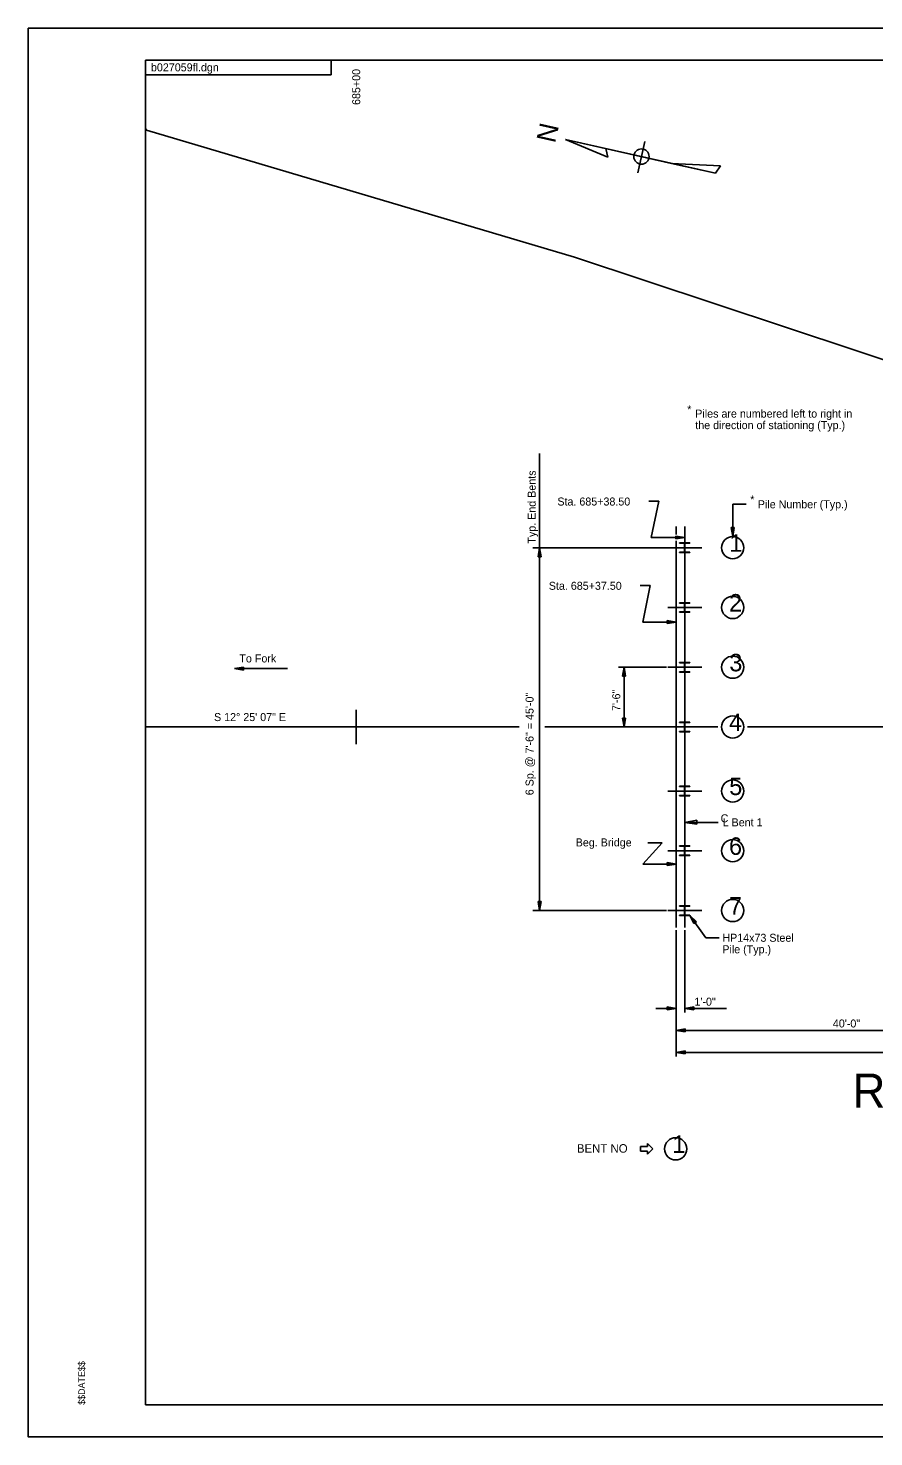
# Model space of a CAD drawing. Extents: x -463 to -191, y 251 to 416.
# Drawn here: x -462.9 to -363.8, y 251.4 to 416.4 of the extents above; entities that cross this region are included whole.
import ezdxf

# ---------------------------------------------------------------- set-up
doc = ezdxf.new("R2010")
doc.units = 0
for name, color, linetype in [('BR_AUTO DIMENSION', 7, 'Continuous'), ('BR_BORDER LINES', 7, 'Continuous'), ('BR_STRUCTURAL STEEL', 7, 'Continuous'), ('BR_TEXT', 7, 'Continuous'), ('Default', 7, 'Continuous'), ('RD_SHT_IplotShp', 7, 'Continuous')]:
    doc.layers.add(name, color=color, linetype=linetype)

# ---------------------------------------------------------------- blocks, each defined once
blk = doc.blocks.new('ARROW1')
at = {"layer": 'Default'}
for p, q in [((0.0001, 33.5999), (-14.3999, 19.1999)), ((-14.3999, 19.1999), (-6.3999, 19.1999)), ((-6.3999, 19.1999), (-6.3999, -0.0001)), ((14.4001, 19.1999), (0.0001, 33.5999)), ((6.4001, -0.0001), (6.4001, 19.1999)), ((6.4001, 19.1999), (14.4001, 19.1999)), ((-6.3999, -0.0001), (6.4001, -0.0001))]:
    blk.add_line(p, q, dxfattribs=at)

msp = doc.modelspace()

# ---------------------------------------------------------------- linework, layer by layer
at = {"layer": 'BR_AUTO DIMENSION'}
for p, q in [((-382.36, 399.46), (-399.92, 403.41)), ((-399.92, 403.41), (-394.95, 401.34)), ((-382.36, 399.46), (-399.92, 403.41)), ((-399.92, 403.41), (-387.5, 400.61)), ((-399.92, 403.41), (-394.95, 401.34)), ((-399.92, 403.41), (-382.36, 399.46)), ((-382.36, 399.46), (-399.92, 403.41)), ((-390.62, 403.18), (-391.45, 399.5)), ((-394.95, 401.34), (-395.18, 402.34)), ((-394.95, 401.34), (-395.18, 402.34)), ((-381.76, 400.32), (-387.5, 400.61)), ((-382.36, 399.46), (-387.5, 400.61)), ((-387.5, 400.61), (-381.76, 400.32)), ((-387.5, 400.61), (-381.76, 400.32)), ((-382.36, 399.46), (-381.76, 400.32)), ((-381.76, 400.32), (-382.36, 399.46)), ((-381.76, 400.32), (-382.36, 399.46)), ((-402.95, 313.09), (-402.95, 366.63)), ((-390.17, 361.05), (-388.98, 361.05)), ((-388.98, 361.05), (-389.86, 356.78)), ((-380.32, 360.69), (-378.76, 360.69)), ((-380.32, 360.69), (-380.32, 356.89)), ((-385.94, 356.78), (-389.86, 356.78)), ((-385.94, 356.78), (-387, 356.96)), ((-387, 356.96), (-387, 356.61)), ((-387, 356.61), (-385.94, 356.78)), ((-380.32, 356.89), (-380.5, 357.94)), ((-380.5, 357.94), (-380.15, 357.94)), ((-380.15, 357.94), (-380.32, 356.89)), ((-403.76, 355.59), (-388.09, 355.59)), ((-402.95, 355.59), (-403.12, 354.53)), ((-402.77, 354.53), (-402.95, 355.59)), ((-388.09, 355.59), (-387.94, 355.59)), ((-403.12, 354.53), (-402.77, 354.53)), ((-391.17, 351.17), (-389.98, 351.17)), ((-389.98, 351.17), (-390.86, 346.88)), ((-386.95, 346.88), (-390.86, 346.88)), ((-386.95, 346.88), (-388, 347.06)), ((-388, 347.06), (-388, 346.7)), ((-388, 346.7), (-386.95, 346.88)), ((-438.71, 341.43), (-437.65, 341.61)), ((-437.65, 341.61), (-437.65, 341.26)), ((-393.71, 341.59), (-388.09, 341.59)), ((-393.22, 340.53), (-393.04, 341.59)), ((-393.04, 334.59), (-393.04, 341.59)), ((-393.04, 341.59), (-392.87, 340.53)), ((-437.65, 341.26), (-438.71, 341.43)), ((-438.71, 341.43), (-432.51, 341.43)), ((-392.87, 340.53), (-393.22, 340.53)), ((-392.87, 335.64), (-393.22, 335.64)), ((-393.22, 335.64), (-393.04, 334.59)), ((-393.04, 334.59), (-392.87, 335.64)), ((-385.94, 323.42), (-384.54, 323.66)), ((-382.03, 323.42), (-385.94, 323.42)), ((-384.54, 323.19), (-385.94, 323.42)), ((-384.54, 323.66), (-384.54, 323.19)), ((-388.61, 321.02), (-390.85, 318.53)), ((-390.28, 321.02), (-388.61, 321.02)), ((-386.93, 318.53), (-390.85, 318.53)), ((-386.93, 318.53), (-387.99, 318.71)), ((-387.99, 318.71), (-387.99, 318.36)), ((-387.99, 318.36), (-386.93, 318.53)), ((-402.95, 313.09), (-403.12, 314.14)), ((-403.12, 314.14), (-402.77, 314.14)), ((-402.77, 314.14), (-402.95, 313.09)), ((-403.76, 313.09), (-388.09, 313.09)), ((-383.47, 309.88), (-385.33, 312.52)), ((-385.33, 312.52), (-384.87, 311.56)), ((-384.58, 311.76), (-385.33, 312.52)), ((-386.94, 310.78), (-386.94, 295.98)), ((-385.94, 310.78), (-385.94, 301.13)), ((-384.87, 311.56), (-384.58, 311.76)), ((-383.47, 309.88), (-381.91, 309.88)), ((-389.33, 301.63), (-386.94, 301.63)), ((-388, 301.45), (-388, 301.8)), ((-388, 301.8), (-386.94, 301.63)), ((-386.94, 301.63), (-388, 301.45)), ((-384.89, 301.8), (-385.94, 301.63)), ((-385.94, 301.63), (-381.05, 301.63)), ((-385.94, 301.63), (-384.89, 301.45)), ((-384.89, 301.45), (-384.89, 301.8)), ((-386.94, 299.05), (-385.89, 299.22)), ((-386.94, 299.05), (-256.94, 299.05)), ((-385.89, 298.87), (-386.94, 299.05)), ((-385.89, 299.22), (-385.89, 298.87)), ((-386.94, 296.47), (-385.89, 296.65)), ((-386.94, 296.47), (-256.94, 296.47)), ((-385.89, 296.29), (-386.94, 296.47)), ((-385.89, 296.65), (-385.89, 296.29))]:
    msp.add_line(p, q, dxfattribs=at)
for centre, radius in [((-391.02, 401.41), 0.9), ((-380.32, 355.59), 1.3), ((-380.32, 348.59), 1.3), ((-380.32, 341.59), 1.3), ((-380.32, 334.59), 1.3), ((-380.32, 327.09), 1.3), ((-380.32, 320.09), 1.3), ((-380.32, 313.09), 1.3), ((-387.01, 285.17), 1.3)]:
    msp.add_circle(centre, radius, dxfattribs=at)
at = {"layer": 'BR_BORDER LINES'}
for p, q in [((-462.88, 416.45), (-192.88, 416.45)), ((-449.13, 255.19), (-449.13, 412.69)), ((-196.63, 412.69), (-449.13, 412.69)), ((-427.38, 412.69), (-427.38, 410.99)), ((-449.13, 410.99), (-427.38, 410.99)), ((-449.13, 255.19), (-196.63, 255.19)), ((-462.88, 251.45), (-192.88, 251.45))]:
    msp.add_line(p, q, dxfattribs=at)
at = {"layer": 'BR_STRUCTURAL STEEL'}
for p, q in [((-386.55, 356.15), (-385.33, 356.15)), ((-386.55, 356.11), (-386.55, 356.15)), ((-386.55, 356.11), (-386.01, 356.11)), ((-386.55, 355.02), (-386.55, 355.06)), ((-386.55, 355.06), (-386.01, 355.06)), ((-386.55, 355.02), (-385.33, 355.02)), ((-385.96, 355.12), (-385.96, 356.06)), ((-385.92, 355.12), (-385.92, 356.06)), ((-385.87, 356.11), (-385.33, 356.11)), ((-385.87, 355.06), (-385.33, 355.06)), ((-385.33, 356.11), (-385.33, 356.15)), ((-385.33, 355.02), (-385.33, 355.06)), ((-386.55, 349.15), (-385.33, 349.15)), ((-386.55, 349.11), (-386.55, 349.15)), ((-386.55, 349.11), (-386.01, 349.11)), ((-385.96, 348.12), (-385.96, 349.06)), ((-385.92, 348.12), (-385.92, 349.06)), ((-385.87, 349.11), (-385.33, 349.11)), ((-385.33, 349.11), (-385.33, 349.15)), ((-386.55, 348.02), (-386.55, 348.06)), ((-386.55, 348.06), (-386.01, 348.06)), ((-386.55, 348.02), (-385.33, 348.02)), ((-385.87, 348.06), (-385.33, 348.06)), ((-385.33, 348.02), (-385.33, 348.06)), ((-386.55, 342.15), (-385.33, 342.15)), ((-386.55, 342.11), (-386.55, 342.15)), ((-386.55, 342.11), (-386.01, 342.11)), ((-385.96, 341.12), (-385.96, 342.06)), ((-385.92, 341.12), (-385.92, 342.06)), ((-385.87, 342.11), (-385.33, 342.11)), ((-385.33, 342.11), (-385.33, 342.15)), ((-386.55, 341.02), (-386.55, 341.06)), ((-386.55, 341.06), (-386.01, 341.06)), ((-386.55, 341.02), (-385.33, 341.02)), ((-385.87, 341.06), (-385.33, 341.06)), ((-385.33, 341.02), (-385.33, 341.06)), ((-386.55, 335.15), (-385.33, 335.15)), ((-386.55, 335.11), (-386.55, 335.15)), ((-386.55, 335.11), (-386.01, 335.11)), ((-385.96, 334.12), (-385.96, 335.06)), ((-385.92, 334.12), (-385.92, 335.06)), ((-385.87, 335.11), (-385.33, 335.11)), ((-385.33, 335.11), (-385.33, 335.15)), ((-386.55, 334.02), (-386.55, 334.06)), ((-386.55, 334.06), (-386.01, 334.06)), ((-386.55, 334.02), (-385.33, 334.02)), ((-385.87, 334.06), (-385.33, 334.06)), ((-385.33, 334.02), (-385.33, 334.06)), ((-386.55, 327.65), (-385.33, 327.65)), ((-386.55, 327.65), (-386.55, 327.61)), ((-386.55, 327.61), (-386.01, 327.61)), ((-385.96, 327.56), (-385.96, 326.62)), ((-385.92, 327.56), (-385.92, 326.62)), ((-385.87, 327.61), (-385.33, 327.61)), ((-385.33, 327.65), (-385.33, 327.61)), ((-386.55, 326.56), (-386.01, 326.56)), ((-386.55, 326.56), (-386.55, 326.52)), ((-386.55, 326.52), (-385.33, 326.52)), ((-385.87, 326.56), (-385.33, 326.56)), ((-385.33, 326.56), (-385.33, 326.52)), ((-386.55, 320.65), (-385.33, 320.65)), ((-386.55, 320.65), (-386.55, 320.61)), ((-386.55, 320.61), (-386.01, 320.61)), ((-385.96, 320.56), (-385.96, 319.62)), ((-385.92, 320.56), (-385.92, 319.62)), ((-385.87, 320.61), (-385.33, 320.61)), ((-385.33, 320.65), (-385.33, 320.61)), ((-386.55, 319.56), (-386.01, 319.56)), ((-386.55, 319.56), (-386.55, 319.52)), ((-386.55, 319.52), (-385.33, 319.52)), ((-385.87, 319.56), (-385.33, 319.56)), ((-385.33, 319.56), (-385.33, 319.52)), ((-386.55, 313.65), (-385.33, 313.65)), ((-386.55, 313.65), (-386.55, 313.61)), ((-386.55, 313.61), (-386.01, 313.61)), ((-385.96, 313.56), (-385.96, 312.62)), ((-385.92, 313.56), (-385.92, 312.62)), ((-385.87, 313.61), (-385.33, 313.61)), ((-385.33, 313.65), (-385.33, 313.61)), ((-386.55, 312.56), (-386.01, 312.56)), ((-386.55, 312.56), (-386.55, 312.52)), ((-386.55, 312.52), (-385.33, 312.52)), ((-385.87, 312.56), (-385.33, 312.56)), ((-385.33, 312.56), (-385.33, 312.52))]:
    msp.add_line(p, q, dxfattribs=at)
for centre, start, end in [((-386.02, 356.06), 357.363, 87.363), ((-386.02, 355.12), 272.637, 2.637), ((-385.87, 356.06), 92.637, 182.637), ((-385.87, 355.12), 177.363, 267.363), ((-386.02, 349.06), 357.363, 87.363), ((-385.87, 349.06), 92.637, 182.637), ((-386.02, 348.12), 272.637, 2.637), ((-385.87, 348.12), 177.363, 267.363), ((-386.02, 342.06), 357.363, 87.363), ((-385.87, 342.06), 92.637, 182.637), ((-386.02, 341.12), 272.637, 2.637), ((-385.87, 341.12), 177.363, 267.363), ((-386.02, 335.06), 357.363, 87.363), ((-385.87, 335.06), 92.637, 182.637), ((-386.02, 334.12), 272.637, 2.637), ((-385.87, 334.12), 177.363, 267.363), ((-386.02, 327.56), 357.363, 87.363), ((-385.87, 327.56), 92.637, 182.637), ((-386.02, 326.62), 272.637, 2.637), ((-385.87, 326.62), 177.363, 267.363), ((-386.02, 320.56), 357.363, 87.363), ((-385.87, 320.56), 92.637, 182.637), ((-386.02, 319.62), 272.637, 2.637), ((-385.87, 319.62), 177.363, 267.363), ((-386.02, 313.56), 357.363, 87.363), ((-385.87, 313.56), 92.637, 182.637), ((-386.02, 312.62), 272.637, 2.637), ((-385.87, 312.62), 177.363, 267.363)]:
    msp.add_arc(centre, 0.0544, start, end, dxfattribs=at)
at = {"layer": 'Default'}
for p, q in [((-387.94, 355.59), (-383.94, 355.59)), ((-387.94, 348.59), (-383.94, 348.59)), ((-387.94, 341.59), (-383.94, 341.59)), ((-424.44, 334.59), (-424.44, 336.59)), ((-405.34, 334.59), (-449.13, 334.59)), ((-424.44, 332.59), (-424.44, 334.59)), ((-402.32, 334.59), (-382.06, 334.59)), ((-378.58, 334.59), (-357.52, 334.59)), ((-387.94, 327.09), (-383.94, 327.09)), ((-387.94, 320.09), (-383.94, 320.09)), ((-387.94, 313.09), (-383.94, 313.09))]:
    msp.add_line(p, q, dxfattribs=at)
for points in [[(-449.13, 404.68), (-449.01, 404.51), (-398.85, 389.64)], [(-350.57, 293.78), (-348.07, 367.64), (-357.52, 375.93), (-398.85, 389.64)], [(-386.94, 358.09), (-386.94, 357.15)], [(-385.94, 358.09), (-385.94, 311.09)], [(-386.94, 356.4), (-386.94, 334.59)], [(-386.94, 334.59), (-386.94, 311.09)]]:
    msp.add_lwpolyline(points, dxfattribs=at)
at = {"layer": 'RD_SHT_IplotShp'}
msp.add_lwpolyline([(-462.88, 416.44), (-192.88, 416.44), (-192.88, 251.44), (-462.88, 251.44)], close=True, dxfattribs=at)

# ---------------------------------------------------------------- block references
at = {"layer": 'BR_TEXT', "xscale": 0.042683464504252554, "yscale": 0.042683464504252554, "rotation": -90.00000000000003}
msp.add_blockref('ARROW1', (-391.11, 285.17), dxfattribs=at)

# ---------------------------------------------------------------- texts
at = {"layer": 'BR_AUTO DIMENSION'}
for s, height, rotation, p in [('685+00', 0.938, 90, (-423.97, 407.45)), ('N', 2.25, 77.3194, (-401.15, 402.9))]:
    msp.add_text(s, height=height, rotation=rotation, dxfattribs=at).set_placement(p)
at = {"layer": 'BR_TEXT'}
for s, height, p in [('b027059fl.dgn', 0.9375, (-448.49, 411.39)), ('*', 0.938, (-385.66, 371.33)), ('Piles are numbered left to right in ', 0.9375, (-384.71, 370.83)), ('the direction of stationing (Typ.)', 0.9375, (-384.71, 369.48)), ('Sta. 685+38.50', 0.9375, (-400.87, 360.53)), ('*', 0.938, (-378.27, 360.78)), ('Pile Number (Typ.)', 0.9375, (-377.38, 360.21)), ('1', 2.05, (-380.72, 355.11)), ('Sta. 685+37.50', 0.9375, (-401.87, 350.66)), ('2', 2.05, (-380.75, 348.11)), ('To Fork', 0.938, (-438.13, 342.15)), ('3', 2.05, (-380.72, 341.11)), ('4', 2.05, (-380.76, 334.11)), ('5', 2.05, (-380.73, 326.61)), ('C', 0.938, (-381.74, 323.42)), ('L Bent 1', 0.938, (-381.5, 322.95)), ('Beg. Bridge', 0.9375, (-398.72, 320.6)), ('6', 2.05, (-380.76, 319.61)), ('7', 2.05, (-380.76, 312.61)), ('HP14x73 Steel ', 0.9375, (-381.54, 309.43)), ('Pile (Typ.)', 0.9375, (-381.54, 308.08)), ('1\'-0"', 0.938, (-384.81, 301.94)), ('40\'-0"', 0.938, (-368.59, 299.39)), ('REVISE PILE SPACING AT INTERIOR BENTS', 4, (-366.29, 289.99)), ('1', 2.05, (-387.4, 284.69))]:
    msp.add_text(s, height=height, dxfattribs=at).set_placement(p)
for s, height, rotation, p in [('Typ. End Bents', 0.9375, 90, (-403.41, 356.07)), ('6 Sp. @ 7\'-6" = 45\'-0"', 0.9375, 90, (-403.66, 326.59)), ('7\'-6"', 0.938, 90, (-393.5, 336.46)), ('S 12%%d 25\' 07" E', 0.9375, 0.0097, (-441.1, 335.28)), ('BENT NO', 1, 360, (-398.58, 284.72)), ('$$DATE$$', 0.781, 90, (-456.22, 255.19)), ('$$DATE$$', 0.781, 90, (-456.22, 255.19))]:
    msp.add_text(s, height=height, rotation=rotation, dxfattribs=at).set_placement(p)

doc.saveas('drawing.dxf')
